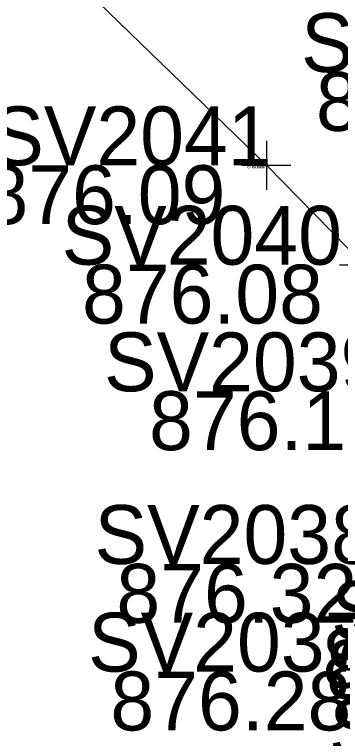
# Model space of a CAD drawing. Extents: x 1475918 to 1480402, y 379235 to 383359.
# Drawn here: x 1480127.89 to 1480134.54, y 379405.99 to 379420.76 of the extents above; entities that cross this region are included whole.
import ezdxf

# ---------------------------------------------------------------- set-up
doc = ezdxf.new("R2010")
doc.units = 0
for name, color, linetype in [('SV_X_Break_Lines', 7, 'Continuous'), ('SV_X_Shot_Marker', 7, 'Continuous'), ('SV_X_Text_Comment', 7, 'Continuous'), ('SV_X_Text_Elevation', 7, 'Continuous'), ('SV_X_Text_Name', 7, 'Continuous')]:
    doc.layers.add(name, color=color, linetype=linetype)

msp = doc.modelspace()

# ---------------------------------------------------------------- linework, layer by layer
at = {"layer": 'SV_X_Break_Lines'}
msp.add_lwpolyline([(1480127.721, 379395.358), (1480131.799, 379398.039), (1480133.273, 379401.352), (1480135.459, 379407.36), (1480135.6, 379409.555), (1480135.793, 379413.076), (1480135.014, 379415.657), (1480133.026, 379417.684), (1480123.803, 379426.624), (1480113.121, 379435.343), (1480106.984, 379440.926), (1480103.73, 379443.918), (1480102.529, 379445.074), (1480100.774, 379445.951), (1480096.595, 379444.059), (1480092.174, 379441.029), (1480086.377, 379436.591)], dxfattribs=at)
at = {"layer": 'SV_X_Shot_Marker'}
for p, q in [((1480133.026, 379418.184), (1480133.026, 379417.184)), ((1480132.526, 379417.684), (1480133.526, 379417.684)), ((1480133.044, 379417.666), (1480133.008, 379417.702)), ((1480133.008, 379417.666), (1480133.044, 379417.701)), ((1480133.026, 379417.684), (1480133.026, 379417.684)), ((1480133.026, 379417.684), (1480133.026, 379417.684)), ((1480134.514, 379415.657), (1480135.514, 379415.657))]:
    msp.add_line(p, q, dxfattribs=at)

# ---------------------------------------------------------------- texts
at = {"layer": 'SV_X_Text_Comment'}
msp.add_text('B', height=0.06, dxfattribs=at).set_placement((1480133.026, 379417.624))
at = {"layer": 'SV_X_Text_Elevation'}
for s, height, p in [('874.19', 1.2, (1480134.035, 379418.386)), ('876.09', 1.2, (1480127.281, 379416.484)), ('876.0884', 0.06, (1480132.636, 379417.624)), ('876.09', 0.06, (1480132.739, 379417.624)), ('876.08', 1.2, (1480129.269, 379414.457)), ('876.18', 1.2, (1480130.635, 379411.876)), ('876.32', 1.2, (1480129.969, 379408.355)), ('874.78', 1.2, (1480134.168, 379407.029)), ('874.75', 1.2, (1480134.241, 379406.805)), ('876.28', 1.2, (1480129.847, 379406.16))]:
    msp.add_text(s, height=height, dxfattribs=at).set_placement(p)
at = {"layer": 'SV_X_Text_Name'}
for s, height, p in [('SV1874', 1.2, (1480133.733, 379419.586)), ('SV2041', 1.2, (1480127.421, 379417.684)), ('SV2041', 0.06, (1480132.746, 379417.684)), ('SV2041', 0.06, (1480132.763, 379417.684)), ('SV2040', 1.2, (1480128.854, 379415.657)), ('SV2039', 1.2, (1480129.718, 379413.076)), ('SV2038', 1.2, (1480129.525, 379409.555)), ('SV1589', 1.2, (1480134.345, 379408.005)), ('SV2037', 1.2, (1480129.393, 379407.36)), ('SV1919', 1.2, (1480134.302, 379405.608))]:
    msp.add_text(s, height=height, dxfattribs=at).set_placement(p)

doc.saveas('drawing.dxf')
